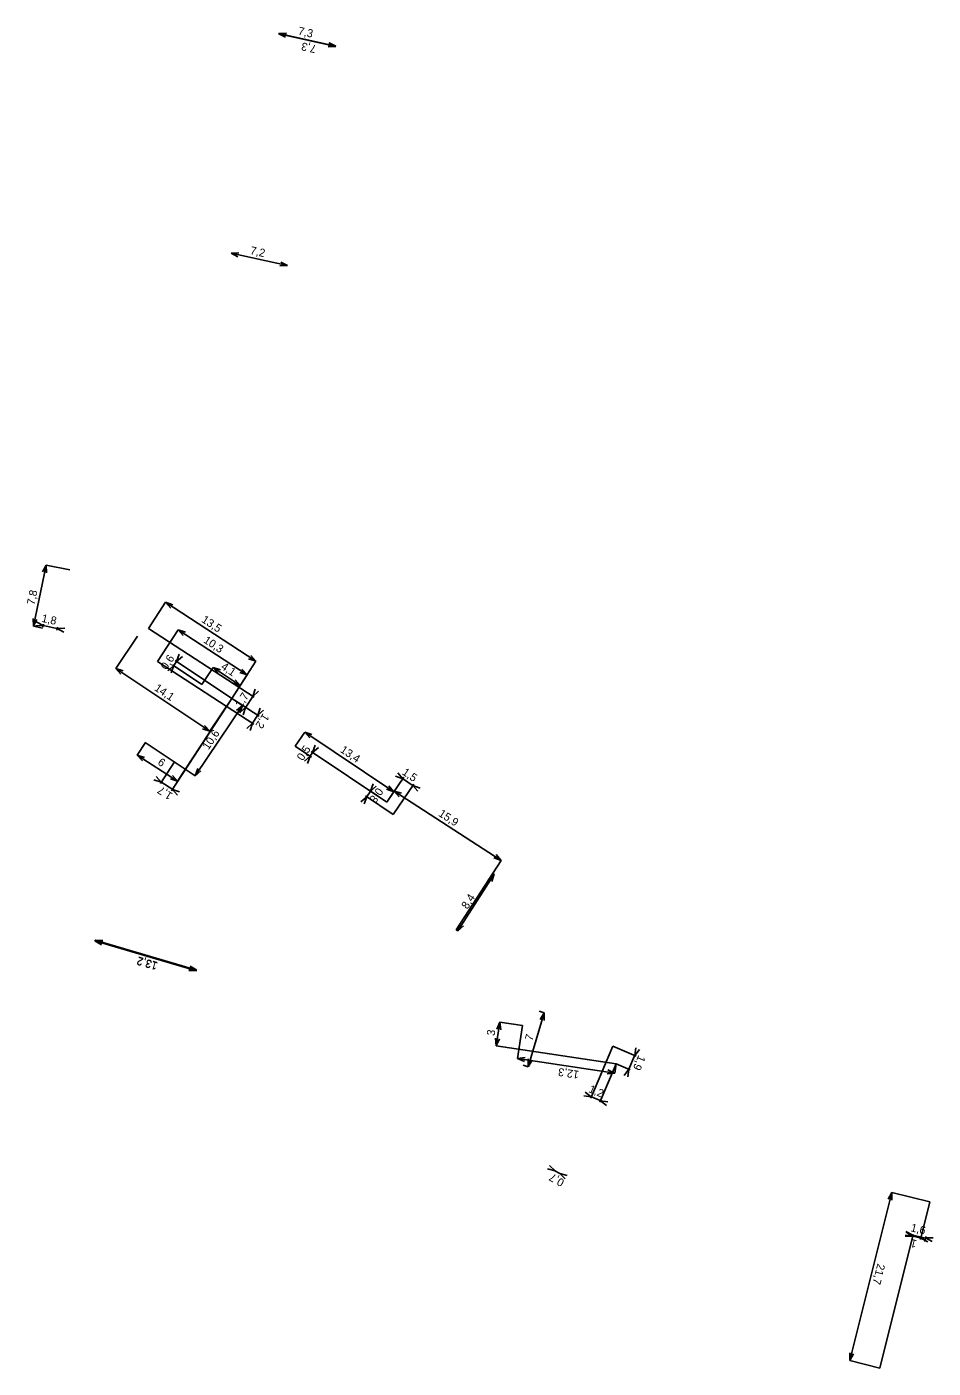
# Model space of a CAD drawing. Extents: x -739737 to -739161, y -1046103 to -1045828.
# Drawn here: x -739737 to -739623.7, y -1045995.6 to -1045827.9 of the extents above; entities that cross this region are included whole.
import ezdxf

# ---------------------------------------------------------------- set-up
doc = ezdxf.new("R2010")
doc.units = 0
for name, color, linetype in [('Kota_NN', 7, 'Continuous'), ('Kota_OPTO', 7, 'Continuous'), ('Kota_VN', 7, 'Continuous')]:
    doc.layers.add(name, color=color, linetype=linetype)

msp = doc.modelspace()

# ---------------------------------------------------------------- linework, layer by layer
at = {"layer": 'Kota_NN'}
for p, q in [((-739736.13, -1045902.86), (-739734.56, -1045895.2)), ((-739734.56, -1045895.2), (-739734.99, -1045896.06)), ((-739731.61, -1045895.81), (-739734.56, -1045895.2)), ((-739734.56, -1045895.2), (-739734.51, -1045896.16)), ((-739736.13, -1045902.86), (-739736.18, -1045901.9)), ((-739736.13, -1045902.86), (-739735.7, -1045902)), ((-739735.01, -1045903.09), (-739736.13, -1045902.86)), ((-739734.94, -1045902.76), (-739735.9, -1045902.8)), ((-739734.94, -1045902.76), (-739735.79, -1045902.31)), ((-739735.14, -1045902.71), (-739732.99, -1045903.18)), ((-739734.9, -1045902.57), (-739734.98, -1045902.95)), ((-739733.14, -1045902.95), (-739733.22, -1045903.34)), ((-739733.18, -1045903.14), (-739732.22, -1045903.1)), ((-739733.18, -1045903.14), (-739732.33, -1045903.58)), ((-739691.98, -1045924.85), (-739691.06, -1045923.44)), ((-739691.06, -1045923.44), (-739677.69, -1045932.11)), ((-739691.06, -1045923.44), (-739690.15, -1045923.73)), ((-739691.06, -1045923.44), (-739690.42, -1045924.15)), ((-739683.32, -1045940.79), (-739677.69, -1045932.11)), ((-739677.69, -1045932.11), (-739678.6, -1045931.81)), ((-739677.69, -1045932.11), (-739678.33, -1045931.39)), ((-739683.11, -1045940.93), (-739678.58, -1045933.83)), ((-739678.58, -1045933.83), (-739679.29, -1045934.48)), ((-739678.58, -1045933.83), (-739678.87, -1045934.74)), ((-739678.78, -1045933.7), (-739678.58, -1045933.83)), ((-739683.11, -1045940.93), (-739682.82, -1045940.01)), ((-739683.11, -1045940.93), (-739682.41, -1045940.28)), ((-739683.32, -1045940.79), (-739683.11, -1045940.93)), ((-739674.31, -1045957.89), (-739672.3, -1045951.16)), ((-739672.94, -1045950.97), (-739672.3, -1045951.16)), ((-739672.3, -1045951.16), (-739672.8, -1045951.98)), ((-739672.3, -1045951.16), (-739672.33, -1045952.12)), ((-739674.31, -1045957.89), (-739674.29, -1045956.93)), ((-739674.31, -1045957.89), (-739673.81, -1045957.07)), ((-739674.95, -1045957.7), (-739674.31, -1045957.89)), ((-739670.95, -1045970.91), (-739671.88, -1045970.67)), ((-739670.95, -1045970.91), (-739671.64, -1045970.24)), ((-739670.2, -1045971.34), (-739671.13, -1045970.81)), ((-739670.95, -1045970.91), (-739670.95, -1045970.91)), ((-739670.37, -1045971.24), (-739670.37, -1045971.24)), ((-739670.37, -1045971.24), (-739669.44, -1045971.48)), ((-739670.37, -1045971.24), (-739669.68, -1045971.91))]:
    msp.add_line(p, q, dxfattribs=at)
at = {"layer": 'Kota_OPTO'}
for p, q in [((-739705.49, -1045828.79), (-739704.53, -1045828.75)), ((-739705.49, -1045828.79), (-739705.49, -1045828.79)), ((-739705.49, -1045828.79), (-739698.35, -1045830.36)), ((-739705.49, -1045828.79), (-739704.64, -1045829.23)), ((-739705.48, -1045828.8), (-739704.52, -1045828.76)), ((-739705.48, -1045828.79), (-739705.48, -1045828.8)), ((-739698.36, -1045830.39), (-739705.48, -1045828.8)), ((-739705.48, -1045828.8), (-739704.63, -1045829.24)), ((-739698.36, -1045830.39), (-739699.21, -1045829.94)), ((-739698.35, -1045830.36), (-739699.2, -1045829.92)), ((-739698.36, -1045830.39), (-739699.32, -1045830.43)), ((-739698.35, -1045830.36), (-739699.31, -1045830.4)), ((-739698.35, -1045830.38), (-739698.36, -1045830.39)), ((-739698.35, -1045830.36), (-739698.35, -1045830.36)), ((-739721.75, -1045903.11), (-739719.63, -1045899.86)), ((-739719.63, -1045899.86), (-739708.34, -1045907.23)), ((-739719.63, -1045899.86), (-739718.72, -1045900.16)), ((-739719.63, -1045899.86), (-739718.99, -1045900.58)), ((-739721.75, -1045903.11), (-739708.55, -1045911.72)), ((-739720.63, -1045907.24), (-739718.06, -1045903.3)), ((-739718.06, -1045903.3), (-739709.44, -1045908.92)), ((-739718.06, -1045903.3), (-739717.15, -1045903.59)), ((-739718.06, -1045903.3), (-739717.42, -1045904.01)), ((-739708.34, -1045907.23), (-739709.25, -1045906.93)), ((-739708.34, -1045907.23), (-739708.98, -1045906.51)), ((-739720.63, -1045907.24), (-739708.6, -1045915.09)), ((-739711.36, -1045911.86), (-739708.34, -1045907.23)), ((-739709.44, -1045908.92), (-739710.35, -1045908.62)), ((-739709.44, -1045908.92), (-739710.08, -1045908.2)), ((-739711.36, -1045911.86), (-739709.44, -1045908.92)), ((-739711.36, -1045911.86), (-739709.45, -1045913.1)), ((-739711.36, -1045911.86), (-739707.94, -1045914.09)), ((-739709.73, -1045913.16), (-739708.61, -1045911.44)), ((-739708.72, -1045911.61), (-739708.42, -1045910.7)), ((-739708.72, -1045911.61), (-739708, -1045910.97)), ((-739709.62, -1045912.99), (-739710.34, -1045913.64)), ((-739709.62, -1045912.99), (-739709.92, -1045913.91)), ((-739708, -1045913.81), (-739708.87, -1045915.15)), ((-739708.11, -1045913.98), (-739707.81, -1045913.07)), ((-739708.11, -1045913.98), (-739707.4, -1045913.34)), ((-739708.76, -1045914.98), (-739709.48, -1045915.62)), ((-739708.76, -1045914.98), (-739709.06, -1045915.89)), ((-739728.44, -1045942.15), (-739728.45, -1045942.17)), ((-739715.76, -1045945.91), (-739728.45, -1045942.17)), ((-739728.45, -1045942.17), (-739727.48, -1045942.19)), ((-739728.45, -1045942.17), (-739727.63, -1045942.67)), ((-739715.76, -1045945.91), (-739716.58, -1045945.41)), ((-739715.76, -1045945.91), (-739716.72, -1045945.89)), ((-739715.76, -1045945.9), (-739715.76, -1045945.91))]:
    msp.add_line(p, q, dxfattribs=at)
at = {"layer": 'Kota_VN'}
for p, q in [((-739711.44, -1045856.23), (-739710.48, -1045856.18)), ((-739711.44, -1045856.23), (-739711.44, -1045856.23)), ((-739711.44, -1045856.23), (-739704.39, -1045857.78)), ((-739711.44, -1045856.23), (-739710.59, -1045856.67)), ((-739704.39, -1045857.78), (-739705.35, -1045857.82)), ((-739704.39, -1045857.78), (-739705.24, -1045857.34)), ((-739704.39, -1045857.78), (-739704.39, -1045857.78)), ((-739723.13, -1045904.09), (-739725.83, -1045908.12)), ((-739718.71, -1045907.94), (-739718.14, -1045907.08)), ((-739711.36, -1045911.86), (-739718.41, -1045907.13)), ((-739718.25, -1045907.24), (-739717.94, -1045906.34)), ((-739718.25, -1045907.24), (-739717.52, -1045906.61)), ((-739725.83, -1045908.12), (-739714.11, -1045915.97)), ((-739725.83, -1045908.12), (-739724.92, -1045908.43)), ((-739725.83, -1045908.12), (-739725.2, -1045908.84)), ((-739718.6, -1045907.77), (-739719.33, -1045908.41)), ((-739718.6, -1045907.77), (-739718.91, -1045908.68)), ((-739715.1, -1045910.12), (-739718.77, -1045907.66)), ((-739715.1, -1045910.12), (-739713.68, -1045908)), ((-739713.68, -1045908), (-739710.29, -1045910.27)), ((-739713.68, -1045908), (-739712.77, -1045908.31)), ((-739713.68, -1045908), (-739713.05, -1045908.72)), ((-739711.36, -1045911.86), (-739710.29, -1045910.27)), ((-739710.29, -1045910.27), (-739711.2, -1045909.96)), ((-739710.29, -1045910.27), (-739710.93, -1045909.54)), ((-739711.36, -1045911.86), (-739718.89, -1045923.41)), ((-739711.36, -1045911.86), (-739718.12, -1045922.23)), ((-739711.36, -1045911.86), (-739714.11, -1045915.97)), ((-739711.36, -1045911.86), (-739710.03, -1045912.75)), ((-739715.92, -1045921.54), (-739710.03, -1045912.75)), ((-739710.03, -1045912.75), (-739710.75, -1045913.39)), ((-739710.03, -1045912.75), (-739710.34, -1045913.66)), ((-739714.11, -1045915.97), (-739714.75, -1045915.24)), ((-739714.11, -1045915.97), (-739715.02, -1045915.66)), ((-739703.42, -1045917.84), (-739702.24, -1045916.07)), ((-739702.24, -1045916.07), (-739691.1, -1045923.54)), ((-739702.24, -1045916.07), (-739701.33, -1045916.38)), ((-739702.24, -1045916.07), (-739701.6, -1045916.8)), ((-739722.13, -1045917.36), (-739723.16, -1045918.94)), ((-739722.16, -1045917.36), (-739715.92, -1045921.54)), ((-739703.42, -1045917.84), (-739701.39, -1045919.2)), ((-739701.67, -1045919.26), (-739701.14, -1045918.47)), ((-739691.98, -1045924.85), (-739701.42, -1045918.52)), ((-739701.25, -1045918.64), (-739700.94, -1045917.73)), ((-739701.25, -1045918.64), (-739700.53, -1045918)), ((-739723.16, -1045918.94), (-739718.12, -1045922.23)), ((-739723.16, -1045918.94), (-739722.25, -1045919.24)), ((-739723.16, -1045918.94), (-739722.52, -1045919.66)), ((-739718.52, -1045919.8), (-739720.28, -1045922.5)), ((-739701.56, -1045919.09), (-739702.28, -1045919.72)), ((-739701.56, -1045919.09), (-739701.87, -1045920)), ((-739720.17, -1045922.34), (-739721.08, -1045922.04)), ((-739720.17, -1045922.34), (-739720.81, -1045921.62)), ((-739718.61, -1045923.35), (-739720.34, -1045922.23)), ((-739718.12, -1045922.23), (-739719.03, -1045921.93)), ((-739718.12, -1045922.23), (-739718.76, -1045921.51)), ((-739715.92, -1045921.54), (-739715.61, -1045920.63)), ((-739715.92, -1045921.54), (-739715.2, -1045920.91)), ((-739691.98, -1045924.85), (-739689.86, -1045921.73)), ((-739689.98, -1045921.9), (-739690.88, -1045921.58)), ((-739689.98, -1045921.9), (-739690.6, -1045921.17)), ((-739690.14, -1045921.79), (-739688.56, -1045922.86)), ((-739718.78, -1045923.24), (-739717.87, -1045923.54)), ((-739718.78, -1045923.24), (-739718.14, -1045923.96)), ((-739693.91, -1045923.3), (-739694.6, -1045924.32)), ((-739691.98, -1045924.85), (-739694.18, -1045923.35)), ((-739694.02, -1045923.47), (-739693.7, -1045922.56)), ((-739694.02, -1045923.47), (-739693.29, -1045922.84)), ((-739691.1, -1045923.54), (-739692.01, -1045923.23)), ((-739691.98, -1045924.85), (-739691.1, -1045923.54)), ((-739691.1, -1045923.54), (-739691.73, -1045922.81)), ((-739691.19, -1045926.39), (-739688.61, -1045922.59)), ((-739688.72, -1045922.75), (-739687.81, -1045923.07)), ((-739688.72, -1045922.75), (-739688.09, -1045923.48)), ((-739694.48, -1045924.15), (-739695.21, -1045924.78)), ((-739694.48, -1045924.15), (-739694.8, -1045925.06)), ((-739691.19, -1045926.39), (-739694.65, -1045924.04)), ((-739728.45, -1045942.18), (-739728.43, -1045942.1)), ((-739715.74, -1045945.84), (-739728.43, -1045942.1)), ((-739728.43, -1045942.1), (-739727.47, -1045942.12)), ((-739728.43, -1045942.1), (-739727.61, -1045942.6)), ((-739715.74, -1045945.84), (-739716.56, -1045945.34)), ((-739715.74, -1045945.84), (-739716.7, -1045945.82)), ((-739715.74, -1045945.85), (-739715.74, -1045945.84)), ((-739678.29, -1045955.3), (-739677.84, -1045952.32)), ((-739677.84, -1045952.32), (-739678.23, -1045953.2)), ((-739675.01, -1045952.74), (-739677.84, -1045952.32)), ((-739677.84, -1045952.32), (-739677.74, -1045953.27)), ((-739675.01, -1045952.74), (-739675.63, -1045956.87)), ((-739678.29, -1045955.3), (-739678.4, -1045954.34)), ((-739678.29, -1045955.3), (-739677.91, -1045954.42)), ((-739663.32, -1045957.54), (-739678.29, -1045955.3)), ((-739663.71, -1045955.34), (-739666.49, -1045961.84)), ((-739663.71, -1045955.34), (-739660.81, -1045956.58)), ((-739660.99, -1045956.5), (-739660.86, -1045955.55)), ((-739660.99, -1045956.5), (-739660.4, -1045955.75)), ((-739675.63, -1045956.87), (-739674.67, -1045956.76)), ((-739663.49, -1045958.69), (-739675.63, -1045956.87)), ((-739675.63, -1045956.87), (-739674.75, -1045957.25)), ((-739660.92, -1045956.32), (-739661.81, -1045958.41)), ((-739663.32, -1045957.54), (-739665.37, -1045962.32)), ((-739663.49, -1045958.69), (-739664.45, -1045958.79)), ((-739663.49, -1045958.69), (-739664.37, -1045958.3)), ((-739663.32, -1045957.54), (-739663.49, -1045958.69)), ((-739663.32, -1045957.54), (-739661.55, -1045958.3)), ((-739661.73, -1045958.22), (-739662.32, -1045958.98)), ((-739661.73, -1045958.22), (-739661.87, -1045959.17)), ((-739666.42, -1045961.66), (-739667.37, -1045961.52)), ((-739666.42, -1045961.66), (-739667.17, -1045961.06)), ((-739666.6, -1045961.58), (-739665.11, -1045962.22)), ((-739665.29, -1045962.14), (-739664.34, -1045962.28)), ((-739665.29, -1045962.14), (-739664.54, -1045962.73)), ((-739628.86, -1045973.6), (-739634.1, -1045994.63)), ((-739628.86, -1045973.6), (-739629.32, -1045974.44)), ((-739624.09, -1045974.79), (-739628.86, -1045973.6)), ((-739628.86, -1045973.6), (-739628.84, -1045974.56)), ((-739624.09, -1045974.79), (-739625.27, -1045979.51)), ((-739630.35, -1045995.57), (-739626.18, -1045978.86)), ((-739626.24, -1045978.94), (-739627.2, -1045978.97)), ((-739626.23, -1045979.06), (-739627.19, -1045979.07)), ((-739626.24, -1045978.94), (-739627.09, -1045978.49)), ((-739626.23, -1045979.06), (-739627.07, -1045978.59)), ((-739626.44, -1045978.89), (-739624.46, -1045979.35)), ((-739625.02, -1045979.36), (-739626.43, -1045979.01)), ((-739626.24, -1045978.93), (-739626.29, -1045979.13)), ((-739624.75, -1045979.73), (-739624.61, -1045979.11)), ((-739624.65, -1045979.3), (-739623.69, -1045979.27)), ((-739625.22, -1045979.31), (-739624.26, -1045979.29)), ((-739625.22, -1045979.31), (-739624.38, -1045979.78)), ((-739624.65, -1045979.3), (-739623.8, -1045979.75)), ((-739634.1, -1045994.63), (-739634.12, -1045993.67)), ((-739634.1, -1045994.63), (-739633.64, -1045993.79)), ((-739630.35, -1045995.57), (-739634.1, -1045994.63))]:
    msp.add_line(p, q, dxfattribs=at)

# ---------------------------------------------------------------- texts
at = {"layer": 'Kota_NN'}
for s, rotation, p in [('7,8', 78.4657, (-739736, -1045900.25)), ('1,8', 347.6702, (-739735.19, -1045902.29)), ('15,9', 327.0393, (-739685.61, -1045926.49)), ('8,4', 57.4038, (-739681.9, -1045938.28)), ('7', 73.3337, (-739673.79, -1045954.73)), ('0,7', 150.5284, (-739669.7, -1045972.08))]:
    msp.add_text(s, height=1, rotation=rotation, dxfattribs=at).set_placement(p)
at = {"layer": 'Kota_OPTO'}
for s, rotation, p in [('7,3', 347.5839, (-739703.13, -1045828.9)), ('7,3', 167.4442, (-739700.71, -1045830.27)), ('13,5', 326.8949, (-739715.22, -1045902.26)), ('10,3', 326.8951, (-739714.98, -1045904.82)), ('1,7', 56.8951, (-739710.18, -1045913.12)), ('1,2', 236.895, (-739707.42, -1045913.66)), ('13,2', 163.5753, (-739720.55, -1045944.91))]:
    msp.add_text(s, height=1, rotation=rotation, dxfattribs=at).set_placement(p)
at = {"layer": 'Kota_VN'}
for s, rotation, p in [('7,2', 347.584, (-739709.12, -1045856.33)), ('0,6', 56.1669, (-739719.5, -1045908.39)), ('4,1', 326.1672, (-739712.8, -1045908.11)), ('14,1', 326.1684, (-739721.12, -1045910.79)), ('10,6', 56.1675, (-739714.27, -1045918.37)), ('0,5', 56.1667, (-739702.48, -1045919.74)), ('13,4', 326.1669, (-739697.89, -1045918.51)), ('6', 326.8939, (-739720.7, -1045920.07)), ('1,5', 325.8243, (-739690.15, -1045921.3)), ('1,7', 146.8949, (-739718.66, -1045923.8)), ('0,8', 235.8246, (-739693.17, -1045922.94)), ('13,2', 163.5753, (-739720.53, -1045944.84)), ('3', 81.4806, (-739678.51, -1045954.08)), ('1,9', 246.8014, (-739660.51, -1045956.38)), ('12,3', 171.4815, (-739667.9, -1045958.43)), ('1,2', 336.8014, (-739666.84, -1045961.04)), ('1,6', 347.0521, (-739626.57, -1045978.45)), ('1', 165.9932, (-739625.66, -1045979.61)), ('21,7', 255.9934, (-739630.65, -1045982.45))]:
    msp.add_text(s, height=1, rotation=rotation, dxfattribs=at).set_placement(p)

doc.saveas('drawing.dxf')
